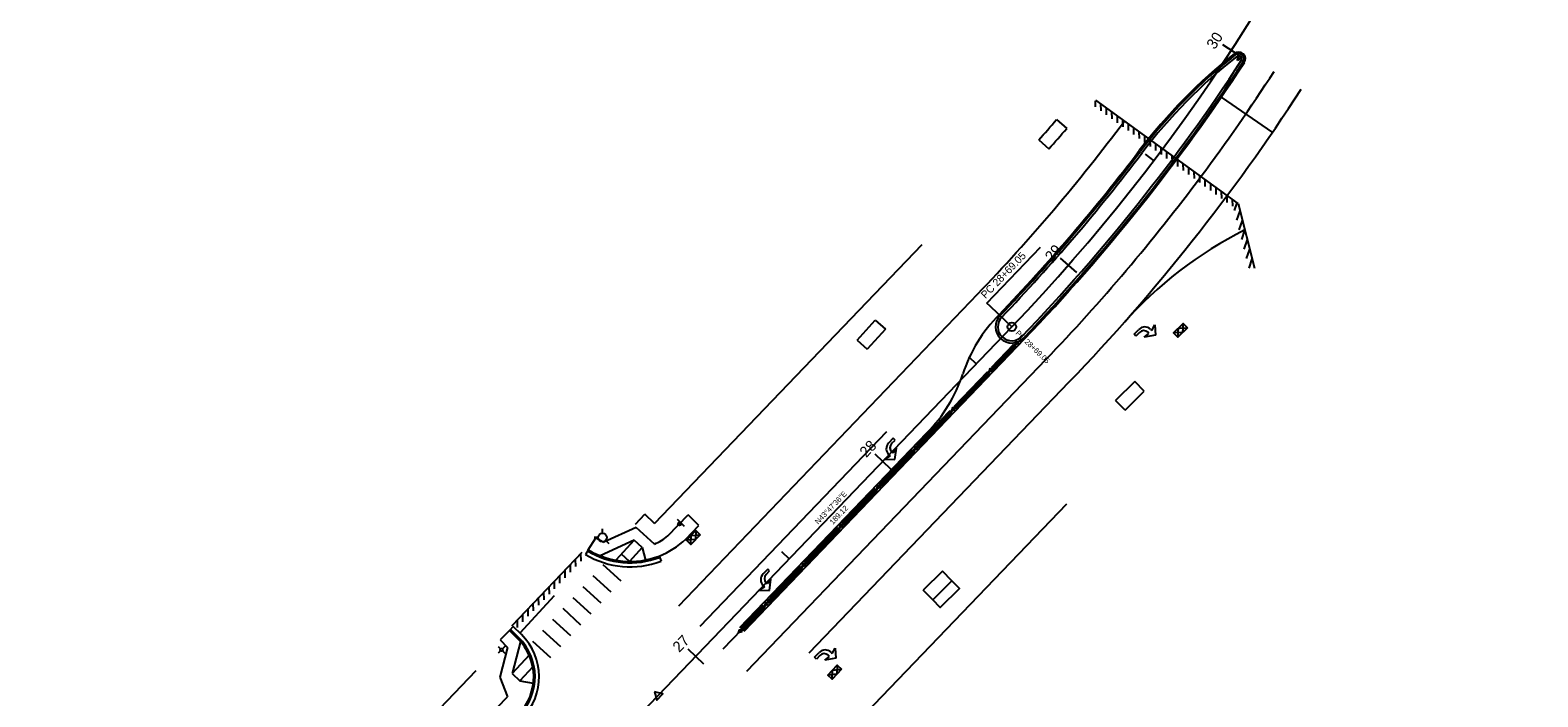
# Model space of a CAD drawing. Extents: x 2377903 to 2496516, y 664638 to 732785.
# Drawn here: x 2378840 to 2379398, y 731307 to 731554 of the extents above; entities that cross this region are included whole.
import ezdxf

# ---------------------------------------------------------------- set-up
doc = ezdxf.new("R2010")
doc.units = 0
for name, color, linetype in [('ALG_CL_BLUE_Horiz', 7, 'Continuous'), ('ALG_CL_BLUE_Horiz-PC-PT-PI', 7, 'Continuous'), ('ALG_CL_BLUE_Horiz-Stationing', 7, 'Continuous'), ('ALG_CL_BLUE_Horiz-Text', 7, 'Continuous'), ('Default', 7, 'Continuous'), ('DES_ROADWAY_Approach', 7, 'Continuous'), ('DES_ROADWAY_Concrete-Pavement', 7, 'Continuous'), ('DES_ROADWAY_Curb-Back', 7, 'Continuous'), ('DES_ROADWAY_Curb-Face', 7, 'Continuous'), ('DES_ROADWAY_Curb-Face-LINE STYLE', 7, 'Continuous'), ('DES_ROADWAY_Edge-of-Pavement', 7, 'Continuous'), ('DES_ROADWAY_Misc-SAW CUT', 7, 'Continuous'), ('DES_ROADWAY_Sidewalk', 7, 'Continuous'), ('ENV_EROSN_Temp-Erosn-Ctrl-Details', 7, 'Continuous'), ('ROW_P_PUA', 7, 'Continuous'), ('TOPO_WTRUTIL_Fire-Hydrant', 7, 'Continuous'), ('TRAF_PAVEMARK_Arrows', 7, 'Continuous'), ('TRAF_PAVEMARK_Stop-Bar', 7, 'Continuous'), ('TRAF_PAVEMARK_White_8-IN', 7, 'Continuous'), ('TRAF_PAVEMARK_White_SKIP 12-38', 7, 'Continuous'), ('TRAF_PAVEMARK_Yellow', 7, 'Continuous'), ('TRAF_PAVEMARK_Yellow-DBL YELLOW', 7, 'Continuous'), ('TRAF_SIGN_Post', 7, 'Continuous'), ('TRAF_WORKZONE_Drum', 7, 'Continuous')]:
    doc.layers.add(name, color=color, linetype=linetype)

# ---------------------------------------------------------------- blocks, each defined once
blk = doc.blocks.new('STSIGN_4')
at = {"layer": 'Default'}
for p, q in [((-0.0223, 0), (-0.0064, 0)), ((0, 0.0223), (0, 0.0064)), ((0.0064, 0), (0.0223, 0)), ((0, -0.0064), (0, -0.0223))]:
    blk.add_line(p, q, dxfattribs=at)
blk.add_circle((0, 0), 0.00635, dxfattribs=at)

msp = doc.modelspace()

# ---------------------------------------------------------------- linework, layer by layer
at = {"layer": 'ALG_CL_BLUE_Horiz'}
for p, q in [((2379072.7, 731307.6), (2379203.59, 731444.12)), ((2378840.27, 731064.93), (2379072.7, 731307.6))]:
    msp.add_line(p, q, dxfattribs=at)
msp.add_arc((2378698.3, 731928.56), 700, 316.20677, 359.74294, dxfattribs=at)
at = {"layer": 'ALG_CL_BLUE_Horiz-PC-PT-PI'}
for p, q in [((2379194.41, 731452.91), (2379214.24, 731473.59)), ((2379195.71, 731451.66), (2379194.41, 731452.91)), ((2379203.59, 731444.12), (2379195.71, 731451.66))]:
    msp.add_line(p, q, dxfattribs=at)
msp.add_circle((2379203.59, 731444.12), 1.6, dxfattribs=at)
at = {"layer": 'ALG_CL_BLUE_Horiz-Stationing'}
for p, q in [((2379281.52, 731548.72), (2379288.22, 731544.36)), ((2379252.92, 731508.07), (2379256.11, 731505.65)), ((2379221.5, 731469.56), (2379227.51, 731464.28)), ((2379187.51, 731433.13), (2379190.4, 731430.36)), ((2379152.91, 731397.04), (2379158.69, 731391.5)), ((2379118.31, 731360.95), (2379121.2, 731358.18)), ((2379083.71, 731324.86), (2379089.48, 731319.32))]:
    msp.add_line(p, q, dxfattribs=at)
msp.add_lwpolyline([(2379071.37, 731308.88), (2379072.26, 731305.81), (2379074.48, 731308.12)], close=True, dxfattribs=at)
at = {"layer": 'DES_ROADWAY_Approach'}
msp.add_lwpolyline([(2379174.31, 731343.01), (2379181.43, 731350.03), (2379184.24, 731347.18), (2379177.12, 731340.16)], close=True, dxfattribs=at)
at = {"layer": 'DES_ROADWAY_Concrete-Pavement'}
for centre, radius, start, end in [((2378698.3, 731928.56), 705.17, 316.20677, 326.82704), ((2379409.7, 731388.78), 198.17, 128.3152, 142.8106), ((2379287.56, 731543.35), 1.17, 326.827, 128.3152), ((2378698.3, 731928.56), 694.83, 316.20677, 322.81063), ((2379203.59, 731444.12), 5.17, 136.2068, 316.2068)]:
    msp.add_arc(centre, radius, start, end, dxfattribs=at)
at = {"layer": 'DES_ROADWAY_Curb-Back'}
for p, q in [((2379196.41, 731428.69), (2379204.68, 731437.31)), ((2379182.57, 731414.25), (2379195.03, 731427.24)), ((2379168.73, 731399.81), (2379181.19, 731412.81)), ((2379154.89, 731385.38), (2379167.35, 731398.37)), ((2379141.05, 731370.94), (2379153.51, 731383.93)), ((2379127.21, 731356.5), (2379139.66, 731369.5)), ((2379113.37, 731342.07), (2379125.82, 731355.06)), ((2379103.71, 731332), (2379111.98, 731340.62)), ((2379020.7, 731328.68), (2379017.69, 731331.66))]:
    msp.add_line(p, q, dxfattribs=at)
for centre, radius, start, end in [((2378698.3, 731928.56), 705.17, 316.20677, 326.82704), ((2379409.7, 731388.78), 198.17, 128.3152, 142.8106), ((2379287.56, 731543.35), 1.17, 326.827, 128.3152), ((2378698.3, 731928.56), 694.83, 316.20677, 322.81063), ((2379203.59, 731444.12), 5.17, 136.2068, 316.2068), ((2379062.33, 731386.88), 29.69, 238.5295, 291.1345), ((2379006.63, 731314.47), 20, 316.0745, 45.3054)]:
    msp.add_arc(centre, radius, start, end, dxfattribs=at)
at = {"layer": 'DES_ROADWAY_Curb-Face'}
for p, q in [((2379196.05, 731429.03), (2379204.32, 731437.66)), ((2379196.77, 731428.34), (2379205.04, 731436.97)), ((2379204.32, 731437.66), (2379205.04, 731436.97)), ((2379196.05, 731429.03), (2379196.77, 731428.34)), ((2379182.21, 731414.6), (2379194.67, 731427.59)), ((2379182.93, 731413.9), (2379195.39, 731426.9)), ((2379194.67, 731427.59), (2379195.39, 731426.9)), ((2379168.37, 731400.16), (2379180.83, 731413.15)), ((2379169.09, 731399.47), (2379181.55, 731412.46)), ((2379180.83, 731413.15), (2379181.55, 731412.46)), ((2379182.21, 731414.6), (2379182.93, 731413.9)), ((2379168.37, 731400.16), (2379169.09, 731399.47)), ((2379154.53, 731385.72), (2379166.99, 731398.72)), ((2379155.25, 731385.03), (2379167.71, 731398.02)), ((2379166.99, 731398.72), (2379167.71, 731398.02)), ((2379140.69, 731371.29), (2379153.14, 731384.28)), ((2379141.41, 731370.59), (2379153.87, 731383.59)), ((2379153.14, 731384.28), (2379153.87, 731383.59)), ((2379154.53, 731385.72), (2379155.25, 731385.03)), ((2379126.85, 731356.85), (2379139.3, 731369.84)), ((2379127.57, 731356.16), (2379140.03, 731369.15)), ((2379139.3, 731369.84), (2379140.03, 731369.15)), ((2379140.69, 731371.29), (2379141.41, 731370.59)), ((2379126.85, 731356.85), (2379127.57, 731356.16)), ((2379113.01, 731342.41), (2379125.46, 731355.4)), ((2379113.73, 731341.72), (2379126.18, 731354.71)), ((2379125.46, 731355.4), (2379126.18, 731354.71)), ((2379103.35, 731332.34), (2379111.62, 731340.97)), ((2379104.07, 731331.65), (2379112.34, 731340.28)), ((2379111.62, 731340.97), (2379112.34, 731340.28)), ((2379113.01, 731342.41), (2379113.73, 731341.72)), ((2379103.35, 731332.34), (2379104.07, 731331.65))]:
    msp.add_line(p, q, dxfattribs=at)
at = {"layer": 'DES_ROADWAY_Curb-Face-LINE STYLE'}
msp.add_line((2379021.05, 731329.04), (2379018.05, 731332.01), dxfattribs=at)
for centre, radius, start, end in [((2379062.33, 731386.88), 30.19, 238.5304, 291.1345), ((2379006.63, 731314.47), 20.5, 316.0745, 45.3054)]:
    msp.add_arc(centre, radius, start, end, dxfattribs=at)
at = {"layer": 'DES_ROADWAY_Edge-of-Pavement'}
for p, q in [((2379287.39, 731489.76), (2379234.66, 731528.05)), ((2379287.39, 731489.76), (2379293.45, 731465.89)), ((2379046.83, 731361.56), (2379045.78, 731359.84)), ((2379018.62, 731333.54), (2379044.56, 731360.62)), ((2379018.62, 731333.54), (2379044.56, 731360.62)), ((2379073.04, 731359.19), (2379073.76, 731357.32)), ((2379019.1, 731333.08), (2379017.69, 731331.66)), ((2379022.11, 731330.11), (2379019.1, 731333.08))]:
    msp.add_line(p, q, dxfattribs=at)
for centre, radius, start, end in [((2379287.56, 731543.35), 2, 326.827, 128.3152), ((2378698.3, 731928.56), 706, 316.20677, 326.82704), ((2379409.7, 731388.78), 199, 128.3152, 142.8106), ((2378698.3, 731928.56), 694, 316.20677, 322.81063), ((2379203.59, 731444.12), 6, 136.2068, 316.2068), ((2379062.32, 731386.91), 31.72, 238.5798, 291.1357), ((2379006.63, 731314.47), 22, 316.0675, 45.3054)]:
    msp.add_arc(centre, radius, start, end, dxfattribs=at)
at = {"layer": 'DES_ROADWAY_Misc-SAW CUT'}
for p, q in [((2379234.59, 731525.63), (2379234.54, 731527.86)), ((2379236.62, 731524.15), (2379236.57, 731526.66)), ((2379238.65, 731522.68), (2379238.6, 731525.19)), ((2379240.69, 731521.2), (2379240.63, 731523.71)), ((2379242.72, 731519.73), (2379242.66, 731522.24)), ((2379244.75, 731518.25), (2379244.7, 731520.76)), ((2379246.78, 731516.78), (2379246.73, 731519.29)), ((2379248.81, 731515.3), (2379248.76, 731517.81)), ((2379250.84, 731513.83), (2379250.79, 731516.34)), ((2379252.88, 731512.35), (2379252.82, 731514.86)), ((2379254.91, 731510.87), (2379254.85, 731513.38)), ((2379256.94, 731509.4), (2379256.89, 731511.91)), ((2379258.97, 731507.92), (2379258.92, 731510.43)), ((2379261, 731506.45), (2379260.95, 731508.96)), ((2379263.03, 731504.97), (2379262.98, 731507.48)), ((2379265.06, 731503.5), (2379265.01, 731506.01)), ((2379267.1, 731502.02), (2379267.04, 731504.53)), ((2379269.13, 731500.55), (2379269.07, 731503.06)), ((2379271.16, 731499.07), (2379271.11, 731501.58)), ((2379273.19, 731497.6), (2379273.14, 731500.11)), ((2379275.22, 731496.12), (2379275.17, 731498.63)), ((2379277.25, 731494.65), (2379277.2, 731497.16)), ((2379279.29, 731493.17), (2379279.23, 731495.68)), ((2379281.32, 731491.7), (2379281.26, 731494.21)), ((2379283.35, 731490.22), (2379283.3, 731492.73)), ((2379285.38, 731488.75), (2379285.33, 731491.26)), ((2379285.99, 731487.16), (2379286.97, 731490.06)), ((2379287.36, 731489.74), (2379287.36, 731489.78)), ((2379286.89, 731483.6), (2379288.07, 731487.07)), ((2379287.79, 731480.04), (2379288.97, 731483.52)), ((2379288.69, 731476.49), (2379289.87, 731479.96)), ((2379289.59, 731472.93), (2379290.78, 731476.4)), ((2379290.5, 731469.38), (2379291.68, 731472.85)), ((2379291.4, 731465.82), (2379292.58, 731469.29)), ((2379040.26, 731353.24), (2379040.2, 731356.07)), ((2379042.21, 731355.28), (2379042.15, 731358.11)), ((2379044.17, 731357.33), (2379044.11, 731360.15)), ((2379046.13, 731359.37), (2379046.13, 731359.54)), ((2379036.34, 731349.15), (2379036.28, 731351.98)), ((2379038.3, 731351.19), (2379038.24, 731354.02)), ((2379030.47, 731343.02), (2379030.41, 731345.85)), ((2379032.43, 731345.06), (2379032.37, 731347.89)), ((2379034.38, 731347.11), (2379034.33, 731349.94)), ((2379024.6, 731336.89), (2379024.54, 731339.72)), ((2379026.56, 731338.93), (2379026.5, 731341.76)), ((2379028.51, 731340.98), (2379028.45, 731343.81)), ((2379018.67, 731333.49), (2379018.67, 731333.59)), ((2379020.68, 731332.8), (2379020.62, 731335.63)), ((2379022.64, 731334.85), (2379022.58, 731337.67))]:
    msp.add_line(p, q, dxfattribs=at)
at = {"layer": 'DES_ROADWAY_Sidewalk'}
for p, q in [((2379220.15, 731520.86), (2379223.91, 731517.56)), ((2379213.56, 731513.33), (2379217.3, 731510.06)), ((2379146.33, 731439.23), (2379153.05, 731446.64)), ((2379153.05, 731446.64), (2379156.81, 731443.22)), ((2379146.33, 731439.23), (2379150.1, 731435.81)), ((2379156.81, 731443.22), (2379150.1, 731435.81)), ((2379249.12, 731423.85), (2379242.01, 731416.83)), ((2379252.61, 731420.32), (2379249.12, 731423.85)), ((2379245.5, 731413.29), (2379252.61, 731420.32)), ((2379245.5, 731413.29), (2379242.01, 731416.83)), ((2379076.25, 731366.67), (2379083.79, 731374.44)), ((2379087.79, 731370.57), (2379083.79, 731374.44)), ((2379064.59, 731369.8), (2379052.63, 731364.32)), ((2379071.32, 731363.63), (2379064.59, 731369.8)), ((2379082.93, 731365.5), (2379087.79, 731370.57)), ((2379046.83, 731361.56), (2379049.58, 731365.95)), ((2379049.58, 731365.95), (2379052.63, 731364.32)), ((2379063.84, 731365.05), (2379051.3, 731359.31)), ((2379063.84, 731365.05), (2379057.07, 731357.66)), ((2379066.79, 731362.35), (2379062.06, 731357.19)), ((2379066.79, 731362.35), (2379063.84, 731365.05)), ((2379066.79, 731362.35), (2379068.04, 731357.74)), ((2379062.06, 731357.19), (2379059.11, 731359.89)), ((2379177.95, 731353.56), (2379170.83, 731346.53)), ((2379174.31, 731343.01), (2379181.43, 731350.03)), ((2379181.43, 731350.03), (2379177.95, 731353.56)), ((2379174.31, 731343.01), (2379170.83, 731346.53)), ((2379017.69, 731331.66), (2379014.24, 731328.15)), ((2379014.24, 731328.15), (2379017, 731325.39)), ((2379017, 731325.39), (2379014.14, 731314.34)), ((2379021.7, 731327.61), (2379018.62, 731315.66)), ((2379024.93, 731322.55), (2379018.62, 731315.66)), ((2379026.3, 731318.13), (2379021.57, 731312.96)), ((2379014.14, 731314.34), (2379016.93, 731307.04)), ((2379018.62, 731315.66), (2379021.57, 731312.96)), ((2379021.57, 731312.96), (2379026.5, 731312.13)), ((2379009.42, 731299.3), (2379016.93, 731307.04))]:
    msp.add_line(p, q, dxfattribs=at)
for centre, radius, start, end in [((2378905.11, 731789.94), 414.31, 318.1155, 319.4984), ((2378947.21, 731754.64), 364.38, 317.837, 319.4095), ((2379063.89, 731381.2), 19.08, 292.9061, 310.3652), ((2379062.33, 731386.88), 29.69, 291.1345, 313.9334)]:
    msp.add_arc(centre, radius, start, end, dxfattribs=at)
at = {"layer": 'ENV_EROSN_Temp-Erosn-Ctrl-Details'}
for points in [[(2379268.6, 731443.78), (2379265.02, 731440.29), (2379263.48, 731441.86), (2379267.06, 731445.35)], [(2379088.22, 731367.11), (2379084.76, 731363.51), (2379083.17, 731365.03), (2379086.63, 731368.64)], [(2379140.54, 731317.3), (2379137.15, 731313.62), (2379135.53, 731315.11), (2379138.92, 731318.79)]]:
    msp.add_lwpolyline(points, close=True, dxfattribs=at)
for points in [[(2379267.06, 731445.35), (2379266.81, 731442.03), (2379263.48, 731441.86)], [(2379265.02, 731440.29), (2379265.27, 731443.61), (2379268.6, 731443.78)], [(2379086.63, 731368.64), (2379086.49, 731365.31), (2379083.17, 731365.03)], [(2379084.76, 731363.51), (2379084.9, 731366.83), (2379088.22, 731367.11)], [(2379138.92, 731318.79), (2379138.84, 731315.46), (2379135.53, 731315.11)], [(2379137.15, 731313.62), (2379137.22, 731316.95), (2379140.54, 731317.3)]]:
    msp.add_lwpolyline(points, dxfattribs=at)
at = {"layer": 'ROW_P_PUA'}
for p, q in [((2379071.35, 731371.22), (2379170.43, 731474.55)), ((2379143.74, 731294.95), (2379223.97, 731378.58)), ((2379064.28, 731371.07), (2379067.74, 731374.68)), ((2379071.35, 731371.22), (2379067.74, 731374.68)), ((2378976.31, 731286.48), (2379005.32, 731316.76))]:
    msp.add_line(p, q, dxfattribs=at)
at = {"layer": 'TOPO_WTRUTIL_Fire-Hydrant'}
for p, q in [((2379052.11, 731367.66), (2379052.09, 731369.25)), ((2379050.55, 731366.06), (2379048.97, 731366.03)), ((2379053.28, 731364.96), (2379054.43, 731363.85))]:
    msp.add_line(p, q, dxfattribs=at)
msp.add_circle((2379052.13, 731366.08), 1.6, dxfattribs=at)
at = {"layer": 'TRAF_PAVEMARK_Arrows'}
for p, q in [((2379248.88, 731441.34), (2379250.6, 731443.14)), ((2379249.55, 731440.7), (2379248.88, 731441.34)), ((2379250.84, 731442.04), (2379249.55, 731440.7)), ((2379252.64, 731440.33), (2379254.36, 731441.68)), ((2379256.79, 731441.07), (2379252.64, 731440.33)), ((2379254.36, 731441.68), (2379253.92, 731442.11)), ((2379254.99, 731443.23), (2379255.44, 731442.8)), ((2379255.44, 731442.8), (2379256.49, 731444.8)), ((2379256.49, 731444.8), (2379256.79, 731441.07)), ((2379159.73, 731402.83), (2379158.01, 731401.04)), ((2379159.11, 731400.84), (2379160.4, 731402.19)), ((2379160.4, 731402.19), (2379159.73, 731402.83)), ((2379158.55, 731396.22), (2379156.6, 731395.08)), ((2379156.6, 731395.08), (2379160.34, 731394.94)), ((2379158.1, 731396.65), (2379158.55, 731396.22)), ((2379159.63, 731397.34), (2379159.18, 731397.77)), ((2379160.91, 731399.12), (2379159.63, 731397.34)), ((2379160.34, 731394.94), (2379160.91, 731399.12)), ((2379113.25, 731354.38), (2379111.53, 731352.59)), ((2379112.64, 731352.39), (2379113.93, 731353.73)), ((2379114.43, 731350.67), (2379113.15, 731348.89)), ((2379113.93, 731353.73), (2379113.25, 731354.38)), ((2379113.86, 731346.49), (2379114.43, 731350.67)), ((2379112.07, 731347.77), (2379110.12, 731346.63)), ((2379110.12, 731346.63), (2379113.86, 731346.49)), ((2379111.63, 731348.2), (2379112.07, 731347.77)), ((2379113.15, 731348.89), (2379112.7, 731349.32)), ((2379130.58, 731321.69), (2379132.3, 731323.48)), ((2379132.54, 731322.39), (2379131.26, 731321.04)), ((2379136.06, 731322.02), (2379135.62, 731322.45)), ((2379136.69, 731323.57), (2379137.14, 731323.14)), ((2379137.14, 731323.14), (2379138.19, 731325.14)), ((2379138.19, 731325.14), (2379138.49, 731321.42)), ((2379131.26, 731321.04), (2379130.58, 731321.69)), ((2379134.34, 731320.67), (2379136.06, 731322.02)), ((2379138.49, 731321.42), (2379134.34, 731320.67))]:
    msp.add_line(p, q, dxfattribs=at)
for centre, radius, start, end in [((2379252.84, 731440.99), 3.1, 46.212, 136.212), ((2379252.41, 731440.54), 2.17, 46.212, 136.212), ((2379160.25, 731398.89), 3.1, 136.2016, 226.2016), ((2379160.68, 731399.34), 2.17, 136.2016, 226.2016), ((2379113.77, 731350.44), 3.1, 136.2016, 226.2016), ((2379114.2, 731350.89), 2.17, 136.2016, 226.2016), ((2379134.54, 731321.33), 3.1, 46.212, 136.212), ((2379134.11, 731320.89), 2.17, 46.212, 136.212)]:
    msp.add_arc(centre, radius, start, end, dxfattribs=at)
at = {"layer": 'TRAF_PAVEMARK_Stop-Bar'}
for p, q in [((2379281.05, 731529.13), (2379300.02, 731516.13)), ((2379052.23, 731356.08), (2379058.87, 731350)), ((2379048.52, 731352.03), (2379055.16, 731345.95)), ((2379034.18, 731344.51), (2379021.52, 731330.68)), ((2379044.81, 731347.97), (2379051.44, 731341.89)), ((2379037.38, 731339.86), (2379044.02, 731333.78)), ((2379041.09, 731343.91), (2379047.73, 731337.83)), ((2379033.66, 731335.8), (2379040.3, 731329.72)), ((2379026.24, 731327.69), (2379032.87, 731321.61)), ((2379029.95, 731331.74), (2379036.59, 731325.66))]:
    msp.add_line(p, q, dxfattribs=at)
at = {"layer": 'TRAF_PAVEMARK_White_8-IN'}
for p, q in [((2379128.65, 731323.33), (2379224.88, 731423.7)), ((2379157.27, 731405.19), (2379088.13, 731333.08))]:
    msp.add_line(p, q, dxfattribs=at)
for centre, radius, start, end in [((2378698.3, 731928.56), 729.5, 316.20677, 327.08885), ((2379357.13, 731345.92), 150, 116.6424, 138.5123)]:
    msp.add_arc(centre, radius, start, end, dxfattribs=at)
at = {"layer": 'TRAF_PAVEMARK_White_SKIP 12-38'}
for p, q in [((2379190.95, 731456.23), (2379080.19, 731340.7)), ((2379216.22, 731432), (2379105.45, 731316.47))]:
    msp.add_line(p, q, dxfattribs=at)
for radius, start, end in [(717.5, 323.30212, 327.08885), (682.5, 316.20677, 323.26512), (717.5, 316.20677, 323.30261)]:
    msp.add_arc((2378698.3, 731928.56), radius, start, end, dxfattribs=at)
at = {"layer": 'TRAF_PAVEMARK_Yellow'}
for p, q in [((2379208.28, 731439.62), (2379104.43, 731331.3)), ((2379102.99, 731332.69), (2379172.13, 731404.8))]:
    msp.add_line(p, q, dxfattribs=at)
for centre, radius, start, end in [((2379409.7, 731388.78), 199.5, 128.3152, 142.8106), ((2379287.56, 731543.35), 2.5, 326.827, 128.3152), ((2378698.3, 731928.56), 706.5, 316.20677, 326.82704), ((2378698.3, 731928.56), 693.5, 316.20677, 322.81063), ((2379237.92, 731409.63), 55.16, 135.0261, 162.0383), ((2379133.33, 731443.44), 54.76, 315.1177, 342.13)]:
    msp.add_arc(centre, radius, start, end, dxfattribs=at)
at = {"layer": 'TRAF_PAVEMARK_Yellow-DBL YELLOW'}
msp.add_line((2379096.79, 731324.78), (2379103.71, 731332), dxfattribs=at)
at = {"layer": 'TRAF_SIGN_Post'}
msp.add_line((2379079.71, 731372.81), (2379082.31, 731370.32), dxfattribs=at)
msp.add_circle((2379080.6, 731371.13), 0.6, dxfattribs=at)
at = {"layer": 'TRAF_WORKZONE_Drum'}
for points in [[(2379287.15, 731542.72), (2379287.29, 731543.97), (2379288.24, 731543.36)], [(2379204.86, 731437.49), (2379205.23, 731438.69), (2379206.04, 731437.92)], [(2379195.2, 731427.42), (2379195.57, 731428.63), (2379196.39, 731427.85)], [(2379181.36, 731412.99), (2379181.73, 731414.19), (2379182.55, 731413.41)], [(2379167.52, 731398.55), (2379167.89, 731399.75), (2379168.7, 731398.97)], [(2379153.68, 731384.11), (2379154.05, 731385.31), (2379154.86, 731384.54)], [(2379139.84, 731369.68), (2379140.21, 731370.88), (2379141.02, 731370.1)], [(2379126, 731355.24), (2379126.37, 731356.44), (2379127.18, 731355.66)], [(2379112.15, 731340.8), (2379112.53, 731342), (2379113.34, 731341.23)], [(2379102.5, 731330.73), (2379102.87, 731331.93), (2379103.69, 731331.16)]]:
    msp.add_lwpolyline(points, close=True, dxfattribs=at)

# ---------------------------------------------------------------- block references
at = {"layer": 'TRAF_SIGN_Post', "xscale": 78.74, "yscale": 78.74000000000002, "rotation": -45.04808418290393}
msp.add_blockref('STSIGN_4', (2379014.75, 731324.44), dxfattribs=at)

# ---------------------------------------------------------------- texts
at = {"layer": 'ALG_CL_BLUE_Horiz-PC-PT-PI'}
msp.add_text('PC 28+69.05', height=2.8, rotation=46.1779, dxfattribs=at).set_placement((2379193.89, 731454.38))
at = {"layer": 'ALG_CL_BLUE_Horiz-Stationing'}
for s, rotation, p in [('30', 56.9251, (2379278.7, 731546.6)), ('29', 48.74, (2379218.46, 731467.91)), ('28', 46.2068, (2379149.73, 731395.46)), ('27', 46.2068, (2379080.52, 731323.27))]:
    msp.add_text(s, height=4, rotation=rotation, dxfattribs=at).set_placement(p)
at = {"layer": 'ALG_CL_BLUE_Horiz-Text'}
for s, rotation, p in [('PC', 316.2068, (2379204.77, 731441.59)), ('28+69.05', 316.2068, (2379208.13, 731438.37)), ('N43°47\'36"E', 46.2068, (2379131.9, 731370.79)), ('189.12', 46.2068, (2379137.35, 731370.69))]:
    msp.add_text(s, height=2, rotation=rotation, dxfattribs=at).set_placement(p)

doc.saveas('drawing.dxf')
